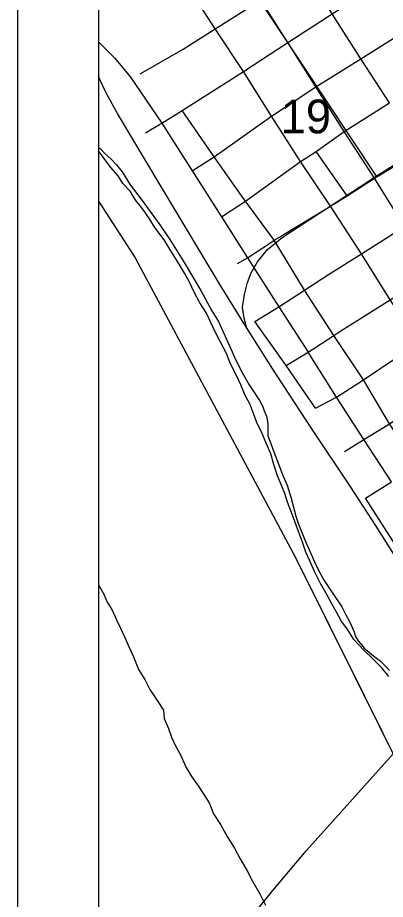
# Model space of a CAD drawing. Extents: x 0 to 34, y 0 to 22.
# Drawn here: x 2 to 2.456, y 15.269 to 16.363 of the extents above; entities that cross this region are included whole.
import ezdxf

# ---------------------------------------------------------------- set-up
doc = ezdxf.new("R2010")
doc.units = 0
for name, color, linetype in [('GM_X_City_Street', 7, 'Continuous'), ('GM_X_Corporation', 7, 'Continuous'), ('GM_X_County_Road', 7, 'Continuous'), ('GM_X_Major_River', 7, 'Continuous'), ('GM_X_Rail_Line', 7, 'Continuous'), ('GM_X_Section_Text', 7, 'Continuous'), ('GM_X_State_Route', 7, 'Continuous'), ('SH_Data', 7, 'Continuous')]:
    doc.layers.add(name, color=color, linetype=linetype)

msp = doc.modelspace()

# ---------------------------------------------------------------- linework, layer by layer
at = {"layer": 'GM_X_City_Street'}
for p, q in [((2.1584, 16.2201), (2.1759, 16.2305)), ((2.4082, 16.142), (2.3698, 16.1972)), ((2.3235, 16.0044), (2.3553, 16.0252)), ((2.2937, 15.9863), (2.3235, 16.0044)), ((2.3327, 15.9317), (2.3601, 15.9483)), ((2.4309, 15.767), (2.463, 15.7871))]:
    msp.add_line(p, q, dxfattribs=at)
for points in [[(2.3346, 16.3321), (2.3012, 16.3848), (2.2686, 16.4364), (2.236, 16.4885), (2.2075, 16.5308), (2.1653, 16.5976), (2.1485, 16.6172), (2.1338, 16.6332), (2.1324, 16.6347), (2.1, 16.6709)], [(2.4607, 16.2573), (2.425, 16.312), (2.3895, 16.3678), (2.3566, 16.4206), (2.3236, 16.4724), (2.2903, 16.5234)], [(2.1519, 16.2934), (2.2052, 16.3239), (2.2445, 16.3493), (2.3012, 16.3848), (2.3566, 16.4206), (2.4114, 16.4556), (2.4553, 16.4836)], [(2.426, 16.0699), (2.3876, 16.1293), (2.3503, 16.1847), (2.3143, 16.2409), (2.2798, 16.2963), (2.2445, 16.3493), (2.2119, 16.4), (2.1818, 16.4529)], [(2.1759, 16.2305), (2.1785, 16.2321), (2.2037, 16.2478), (2.2798, 16.2963), (2.3346, 16.3321), (2.3895, 16.3678), (2.4439, 16.403), (2.4879, 16.4299)], [(2.3104, 16.2381), (2.3143, 16.2409), (2.3696, 16.2771), (2.425, 16.312), (2.4809, 16.3471), (2.5267, 16.3771)], [(2.1, 16.3331), (2.12, 16.3131), (2.1397, 16.289), (2.1785, 16.2321), (2.2162, 16.1729), (2.2524, 16.1158), (2.2848, 16.0653), (2.3235, 16.0044), (2.3601, 15.9483)], [(2.4045, 16.222), (2.3696, 16.2771), (2.3346, 16.3321)], [(2.2777, 16.1418), (2.2434, 16.1905), (2.2037, 16.2478)], [(2.2162, 16.1729), (2.2434, 16.1905), (2.3104, 16.2381)], [(2.328, 16.0931), (2.3876, 16.1293), (2.4082, 16.142), (2.4421, 16.1638), (2.4981, 16.1978), (2.5532, 16.2332)], [(2.3553, 16.0252), (2.3853, 16.0445), (2.426, 16.0699), (2.4793, 16.104), (2.5345, 16.1395), (2.5908, 16.1752), (2.6467, 16.2093), (2.6843, 16.233)], [(2.2524, 16.1158), (2.2822, 16.1353), (2.3503, 16.1847), (2.3698, 16.1972), (2.4045, 16.222)], [(3.1426, 15.061), (3.1075, 15.1168), (3.0723, 15.1734), (3.037, 15.2286), (2.9788, 15.3223), (2.943, 15.3775), (2.907, 15.4324), (2.8722, 15.488), (2.8362, 15.5439), (2.7981, 15.6037), (2.7635, 15.6594), (2.7272, 15.7145), (2.691, 15.7704), (2.6499, 15.8363), (2.619, 15.8863), (2.5848, 15.9396), (2.5662, 15.9686), (2.5508, 15.9914), (2.5151, 16.0468), (2.4793, 16.104), (2.4421, 16.1638), (2.4045, 16.222)], [(2.3553, 16.0252), (2.3178, 16.0869), (2.2822, 16.1353), (2.2777, 16.1418)], [(2.3689, 15.8785), (2.3951, 15.8924), (2.4283, 15.9138), (2.4678, 15.9401), (2.498, 15.9588), (2.5508, 15.9914), (2.6069, 16.0261), (2.6631, 16.0612), (2.7181, 16.0981), (2.77, 16.1313)], [(2.3045, 16.0781), (2.3178, 16.0869), (2.3272, 16.0926), (2.328, 16.0931)], [(2.2723, 16.0579), (2.2848, 16.0653), (2.3037, 16.0776), (2.3045, 16.0781)], [(2.5943, 15.8011), (2.5628, 15.8516), (2.5299, 15.9063), (2.498, 15.9588), (2.4615, 16.0131), (2.426, 16.0699)], [(2.4048, 15.8249), (2.4287, 15.8397), (2.4606, 15.8592), (2.5299, 15.9063), (2.5848, 15.9396), (2.6407, 15.9737), (2.6954, 16.0094), (2.7474, 16.0417)], [(2.8147, 15.3033), (2.7818, 15.3541), (2.7485, 15.4101), (2.7126, 15.4637), (2.6737, 15.5253), (2.6392, 15.58), (2.6034, 15.6355), (2.5685, 15.6921), (2.5348, 15.7445), (2.4948, 15.8071), (2.4606, 15.8592), (2.4283, 15.9138), (2.3916, 15.9689), (2.3553, 16.0252)], [(2.3689, 15.8785), (2.3327, 15.9317), (2.2937, 15.9863)], [(2.5059, 15.6505), (2.4715, 15.7037), (2.4309, 15.767)]]:
    msp.add_lwpolyline(points, dxfattribs=at)
at = {"layer": 'GM_X_Corporation'}
msp.add_lwpolyline([(3.3441, 14.1), (8.9, 14.1), (8.9, 20.9), (2.1, 20.9), (2.1, 16.1353), (2.1457, 16.065), (2.3447, 15.6926), (2.4297, 15.5215), (2.465, 15.4504), (2.4884, 15.4033), (2.5769, 15.2135), (2.7849, 14.8403), (2.8931, 14.6544), (3.0297, 14.4867), (3.1386, 14.3654), (3.228, 14.2415)], close=True, dxfattribs=at)
for points in [[(2.1, 19.6396), (2.1, 16.1353), (2.1457, 16.065), (2.3447, 15.6926), (2.4297, 15.5215), (2.465, 15.4504), (2.4884, 15.4033), (2.5769, 15.2135), (2.7849, 14.8403), (2.8931, 14.6544), (3.0297, 14.4867), (3.1386, 14.3654), (3.228, 14.2415), (3.3441, 14.1), (5.4627, 14.1)], [(2.1, 17.304), (2.1, 16.1353), (2.1457, 16.065), (2.3447, 15.6926), (2.4884, 15.4033), (2.5769, 15.2135)], [(2.1, 16.551), (2.1, 16.2019), (2.1025, 16.2002), (2.1085, 16.1941), (2.1157, 16.1876), (2.1225, 16.1804), (2.1293, 16.1717), (2.1395, 16.1558), (2.1531, 16.1379), (2.1762, 16.1061), (2.1886, 16.0879), (2.2049, 16.0613), (2.2268, 16.0245), (2.2407, 15.9995), (2.249, 15.9862), (2.2626, 15.9559), (2.2702, 15.938), (2.2785, 15.9221), (2.2868, 15.9077), (2.2909, 15.9012), (2.2996, 15.888), (2.3034, 15.8815), (2.3056, 15.8754), (2.3083, 15.8686), (2.3098, 15.8595), (2.3101, 15.8489), (2.3098, 15.8444), (2.3124, 15.8383), (2.3173, 15.8243), (2.329, 15.7943), (2.3339, 15.783), (2.3388, 15.767), (2.3448, 15.7447), (2.3478, 15.7348), (2.3557, 15.7155), (2.3678, 15.6882), (2.3731, 15.6768), (2.3791, 15.6662), (2.3897, 15.6502), (2.4018, 15.6324), (2.4063, 15.6233), (2.4116, 15.6131), (2.4165, 15.6021), (2.4187, 15.5956), (2.4218, 15.5899), (2.4244, 15.5873), (2.4293, 15.5808), (2.4407, 15.5713), (2.4494, 15.5649), (2.455, 15.5595), (2.4607, 15.5531)]]:
    msp.add_lwpolyline(points, dxfattribs=at)
at = {"layer": 'GM_X_County_Road'}
msp.add_line((2.4045, 16.222), (2.4607, 16.2573), dxfattribs=at)
at = {"layer": 'GM_X_Major_River'}
for points in [[(2.3952, 15.6255), (2.3891, 15.6361), (2.3835, 15.6467), (2.3752, 15.6611), (2.3676, 15.6759), (2.3615, 15.6903), (2.357, 15.7002), (2.3529, 15.7123), (2.3479, 15.7256), (2.3434, 15.7381), (2.3393, 15.7491), (2.3343, 15.762), (2.3309, 15.7726), (2.3272, 15.7821), (2.3219, 15.7946), (2.3173, 15.8086), (2.3136, 15.8219), (2.3079, 15.8352), (2.3015, 15.8503), (2.2966, 15.8598), (2.2924, 15.8708), (2.2875, 15.8841), (2.2818, 15.8943), (2.2765, 15.9076), (2.2709, 15.9201), (2.2633, 15.9345), (2.2588, 15.9466), (2.2508, 15.9614), (2.2452, 15.9724), (2.2384, 15.9864), (2.2338, 15.9963), (2.2259, 16.0092), (2.2187, 16.0225), (2.2119, 16.0365), (2.2066, 16.046), (2.1987, 16.0592), (2.1896, 16.074), (2.1817, 16.0873), (2.17, 16.1028), (2.1632, 16.1135), (2.1549, 16.1256), (2.1465, 16.1362), (2.1394, 16.148), (2.1303, 16.1574), (2.1246, 16.1669), (2.1155, 16.1771), (2.1072, 16.1885), (2.1, 16.1978)], [(2.1, 15.6597), (2.1067, 15.6481), (2.1109, 15.6382), (2.1169, 15.628), (2.1226, 15.6159), (2.1275, 15.6056), (2.1328, 15.5942), (2.137, 15.5848), (2.1434, 15.5704), (2.1498, 15.5544), (2.1574, 15.5419), (2.1638, 15.5298), (2.1729, 15.5161), (2.1808, 15.504), (2.1816, 15.4938), (2.1868, 15.4813), (2.1906, 15.4707), (2.1955, 15.4597), (2.2008, 15.4502), (2.2088, 15.4331), (2.2148, 15.4225), (2.2246, 15.4089), (2.2307, 15.3994), (2.2371, 15.3892), (2.2428, 15.3755), (2.2511, 15.3622), (2.2594, 15.3475), (2.2688, 15.3327), (2.2757, 15.3198), (2.284, 15.3058), (2.2911, 15.2921), (2.3006, 15.2754), (2.307, 15.2622)], [(2.4598, 15.5459), (2.4511, 15.5565), (2.4402, 15.5679), (2.4284, 15.5789), (2.4163, 15.5918), (2.4092, 15.6035), (2.4009, 15.6149), (2.3952, 15.6255)]]:
    msp.add_lwpolyline(points, dxfattribs=at)
at = {"layer": 'GM_X_Rail_Line'}
for points in [[(2.1, 16.6705), (2.1371, 16.6305), (2.4442, 16.1664)], [(2.4442, 16.1664), (2.5483, 16.2319), (2.6691, 16.3062), (2.7204, 16.3356), (2.7612, 16.3582), (2.7771, 16.3744)], [(2.9276, 14.9724), (2.6173, 15.4595), (2.5724, 15.5299), (2.5232, 15.6076), (2.4738, 15.6851), (2.4442, 15.7322), (2.412, 15.7819), (2.3635, 15.8541), (2.3161, 15.9269), (2.2837, 15.9787), (2.2514, 16.0309), (2.1759, 16.1569), (2.1237, 16.2441), (2.1109, 16.2673), (2.1052, 16.2792), (2.1005, 16.2894), (2.1, 16.2907)], [(2.2835, 15.9792), (2.2808, 15.9901), (2.2787, 16.0036), (2.2811, 16.0197), (2.2847, 16.0347), (2.2892, 16.0467), (2.2972, 16.0601), (2.3097, 16.0753), (2.3275, 16.0902), (2.4442, 16.1664)]]:
    msp.add_lwpolyline(points, dxfattribs=at)
at = {"layer": 'GM_X_State_Route'}
for points in [[(2.4003, 15.9744), (2.4615, 16.0131), (2.5151, 16.0468), (2.5232, 16.052)], [(2.3601, 15.9483), (2.3916, 15.9689), (2.4003, 15.9744)], [(2.463, 15.7871), (2.4287, 15.8397), (2.3951, 15.8924), (2.3601, 15.9483)], [(2.2476, 15.1959), (2.3182, 15.2828), (2.3578, 15.3302), (2.4652, 15.4499), (2.4659, 15.4506)]]:
    msp.add_lwpolyline(points, dxfattribs=at)
at = {"layer": 'SH_Data'}
for p, q in [((2, 21), (2, 14)), ((2.1, 20.9), (2.1, 14.1))]:
    msp.add_line(p, q, dxfattribs=at)

# ---------------------------------------------------------------- texts
at = {"layer": 'GM_X_Section_Text'}
msp.add_text('19', height=0.04186, rotation=0, dxfattribs=at).set_placement((2.3259, 16.2195))

doc.saveas('drawing.dxf')
